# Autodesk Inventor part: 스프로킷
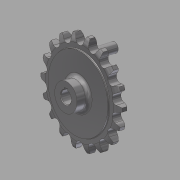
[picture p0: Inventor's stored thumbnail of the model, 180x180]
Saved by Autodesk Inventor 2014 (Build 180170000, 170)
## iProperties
Created: 2016-03
Part Number: 스프로킷
Material: 강철, 탄소
Document SubType Name: Modeling
Designer: mduedu
Density: 7.87 g/cm^3
Mass: 309.145 g
Surface Area: 126.546 cm^2
Volume: 39.2815 cm^3
Appearance: 반광택
Author: mduedu
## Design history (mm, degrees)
sketch "스케치1"
  geometry: L1 (0, 5)-(29.5, 5); L2 (29.5, 5)-(29.5, 4.1); L3 (30, 3.6)-(33.625, 3.6); L4 (40, 2)-(40, 0); L5 (40, 0)-(0, 0); L6 (0, 0)-(0, 5); L7 (0, -5)-(29.5, -5); L8 (29.5, -5)-(29.5, -4.1); L9 (30, -3.6)-(33.625, -3.6); L10 (40, -2)-(40, 0); L11 (0, 0)-(0, -5); A1 r 13.5 centre (33.625, -9.9) between (40, 2) and (33.625, 3.6); A2 r 13.5 centre (33.625, 9.9) between (33.625, -3.6) and (40, -2); A3 r 0.5 centre (30, 4.1) between (29.5, 4.1) and (30, 3.6); A4 r 0.5 centre (30, -4.1) between (30, -3.6) and (29.5, -4.1); 2 further points
  constraints: 22 end point, 8 point on circle, 6 symmetric about line, 5 tangent, 4 centre point, 4 parallel, 4 point on line, 1 equal radius, 1 horizontal, 1 perpendicular, 1 other
  dimensions: "d0" = 80 diameter of L4 L6; "d2" = 59 diameter of L2 L6; "d3" = 1.6 vertical distance of L4.start L3.end; "d4" = 3.6 distance from line of L4.end L3; "d5" = 5 distance between parallel lines of L5 L1; "d6" = 13.5 radius of A1; "d15" = 0.5 radius of A3
revolve "회전1" sketch "스케치1" stored, may be unused: angle "d7" = 90 deg
sketch "스케치2" dims "d8" = 65.2, "d11" = 80
  geometry: L1 (0, 0)-(0, 32.6); A1 r 36.57 centre (0, 0) between (-16.231, 32.771) and (0, 36.57); A2 r 3.97 centre (0, 36.57) between (-3.866, 35.665) and (0, 32.6); A3 r 12.7 centre (-16.231, 32.771) between (-3.866, 35.665) and (-5.534, 39.615); A4 r 12.7 centre (16.231, 32.771) between (5.534, 39.615) and (3.866, 35.665); A5 r 3.97 centre (0, 36.57) between (0, 32.6) and (3.866, 35.665); A6 r 40 centre (0, 0) between (5.534, 39.615) and (-5.534, 39.615); 2 further points
  constraints: 12 point on circle, 6 centre point, 4 coincident, 3 symmetric about line, 2 end point, 1 point on line, 1 tangent, 1 vertical, 1 vertical alignment, 7 other
  dimensions: "d10" = 73.14 diameter of A1; "d12" = 12.7 radius of A3
extrude "돌출1" cut sketch "스케치2" stored distance "d13" = 10; taper "d14" = 0 deg
sketch "스케치3"
  geometry: C1 r 11 at (0, 0); 1 further point
  constraints: 1 centre point, 1 coincident
  dimensions: "d19" = 22 diameter of C1
extrude "돌출2" join sketch "스케치3" distance "d20" = 10; taper "d21" = 0 deg
fillet "모깎기1" dims "d22" = 3
sketch "스케치4"
  geometry: L1 (-1.5, 0)-(1.5, 0); L2 (1.5, 0)-(1.5, 6.4); L3 (1.5, 6.4)-(-1.5, 6.4); L4 (-1.5, 6.4)-(-1.5, 0); C1 r 5 at (0, 0); 2 further points
  constraints: 8 end point, 2 coincident, 2 parallel, 1 centre point, 1 horizontal, 1 midpoint, 1 perpendicular
  dimensions: "d23" = 10 diameter of C1; "d25" = 3 distance of L2.end L3.end; "d26" = 6.4 distance of L1.end L2.end
extrude "돌출3" cut sketch "스케치4" stored distance "d27" = 8; taper "d28" = 0 deg
chamfer "모따기1" distance "d29" = 0.5; stored, may be unused: second distance "d30" = 2, angle "d31" = 45 deg
sketch "스케치5" dims "d33" = 48
  geometry: C1 r 4 at (0, 24); 2 further points
  constraints: 2 vertical alignment, 1 centre point, 1 coincident, 2 other
  dimensions: "d32" = 8 diameter of C1
extrude "돌출4" join sketch "스케치5" distance "d34" = 20; taper "d35" = 0 deg
fillet "모깎기2" dims "d36" = 1
hole "구멍1" diameter "d39" = 3.242; stored, may be unused: countersink angle "d43" = 90 deg, drill point angle "d45" = 118 deg; dims "d40" = 8, "d41" = 4, "d42" = 2, "d44" = 10, "d46" = 10, "d47" = 10
node "솔리드1"
pattern_circular "원형 패턴1" dims angle "d17" = 360 deg
